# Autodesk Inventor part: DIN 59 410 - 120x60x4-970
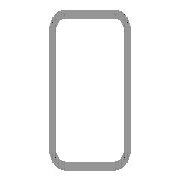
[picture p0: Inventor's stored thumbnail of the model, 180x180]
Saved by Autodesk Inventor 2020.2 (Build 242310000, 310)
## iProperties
Manager: www.cadconsulting.pl
Company: Fabian Stasiak CAD Consulting
Created: 2015-02
Part Number: DIN 59 410 - 120x60x4-970
Material: Stal, miękka
Description: Rurki stalowe o przekroju prostokątnym formowane na gorąco
Document SubType Name: Modellieren
Standard: DIN
Designer: F.Stasiak
Standards Organization: DIN
Language: pl-PL
Size Designation: 120x60x4
Categories: <MemberInstance><Categories><Category DisplayName="Kształtowniki konstrukcyjne" InternalName="089c4875-fa83-4c05-b084-43b9cc11f5ed" Mnemonic="GRDR"><CategoryPar
Stock Number: 120x60x4
Density: 7.85 g/cm^3
Appearance: Częściowo polerowany
Catalog Web Link: www.expertbooks.pl
IsCustomPart: 1
G_L: 970,000 mm
G_W: 60,000 mm
G_H: 120,000 mm
+8458E4FF-DFCE-441F-97C4-4D3776AB817A+CUTDETAIL1: Wytnij
+B13AA665-A8A2-46E3-9D95-F9C71092F1DE+CUTDETAIL2: Wytnij
_CCFamilyMember: 190
_CCFamilyDisplayName: DIN 59410 (Prostokąt) - Rurki stalowe o przekroju prostokątnym formowane na gorąco — Standard DIN 59410 (Prostokąt) został wycofany i zastąpiony przez standard 
_FrameMemberDoc: Frame Member File
_Version: 15.0.0
_GetPNFromCC: 1
Author: F.Stasiak
Subject: Zbiór ćwiczeń. Autodesk Inventor 2020. Kurs Professional
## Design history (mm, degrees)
node "Płaszczyzna początkowa"
node "Płaszczyzna końcowa"
sketch "Szkic"
  geometry: L1 (-22, 60)-(22, 60); L2 (30, 52)-(30, -52); L3 (22, -60)-(-22, -60); L4 (-30, -52)-(-30, 52); L5 (-44.32, 0)-(44.32, 0) reference; L6 (0, -86.32)-(0, 86.32) reference; L7 (-22, 56)-(22, 56); L8 (26, 52)-(26, -52); L9 (22, -56)-(-22, -56); L10 (-26, -52)-(-26, 52); A1 r 8 centre (-22, 52) between (-22, 60) and (-30, 52); A2 r 8 centre (22, 52) between (30, 52) and (22, 60); A3 r 8 centre (22, -52) between (22, -60) and (30, -52); A4 r 8 centre (-22, -52) between (-30, -52) and (-22, -60); A5 r 4 centre (-22, 52) between (-22, 56) and (-26, 52); A6 r 4 centre (22, 52) between (26, 52) and (22, 56); A7 r 4 centre (22, -52) between (22, -56) and (26, -52); A8 r 4 centre (-22, -52) between (-26, -52) and (-22, -56); 3 further points
  constraints: 16 end point, 16 point on circle, 8 centre point, 8 tangent, 6 point on line, 4 parallel, 3 equal radius, 2 perpendicular, 1 horizontal, 7 other
  dimensions: "b" = 60 distance of point (-30, 60) point (30, 60); "ParH" = 120 distance of point (30, 60) point (30, -60); "msp_r" = 8 radius of A1 (= 2 x ParT); "d8" = 30 distance between parallel lines of L4 L6 (= 0.5 x b); "d9" = 60 distance between parallel lines of L5 L1 (= 0.5 x ParH); "d10" = 4 distance between parallel lines of L4 L10 (= ParT)
extrude "Bryła" new body sketch "Szkic" taper "d4" = 0 deg; stored distance "NLG" = 10
node "Driven Length"
  sketch "Sketch2"
    geometry: L1 (0, 0)-(10, 0) reference
    constraints: 2 end point, 1 horizontal
  workplane "Work Plane3"
  sketch "Sketch3"
    geometry: L1 (-2, 60)-(12, 60) reference; L2 (-2, 1030)-(12, 1030) reference
    dimensions: "d14" = 970 distance between parallel lines of L1 L2 (derived)
node "Płaszczyzna konstrukcyjna4"
feature "Podział1"
node "Płaszczyzna konstrukcyjna5"
feature "Podział2"
body "Solid1"
other parameters: "ParT" = 4, "G_L" = 970 (= d14) [user parameter], "d13" = 90 deg
